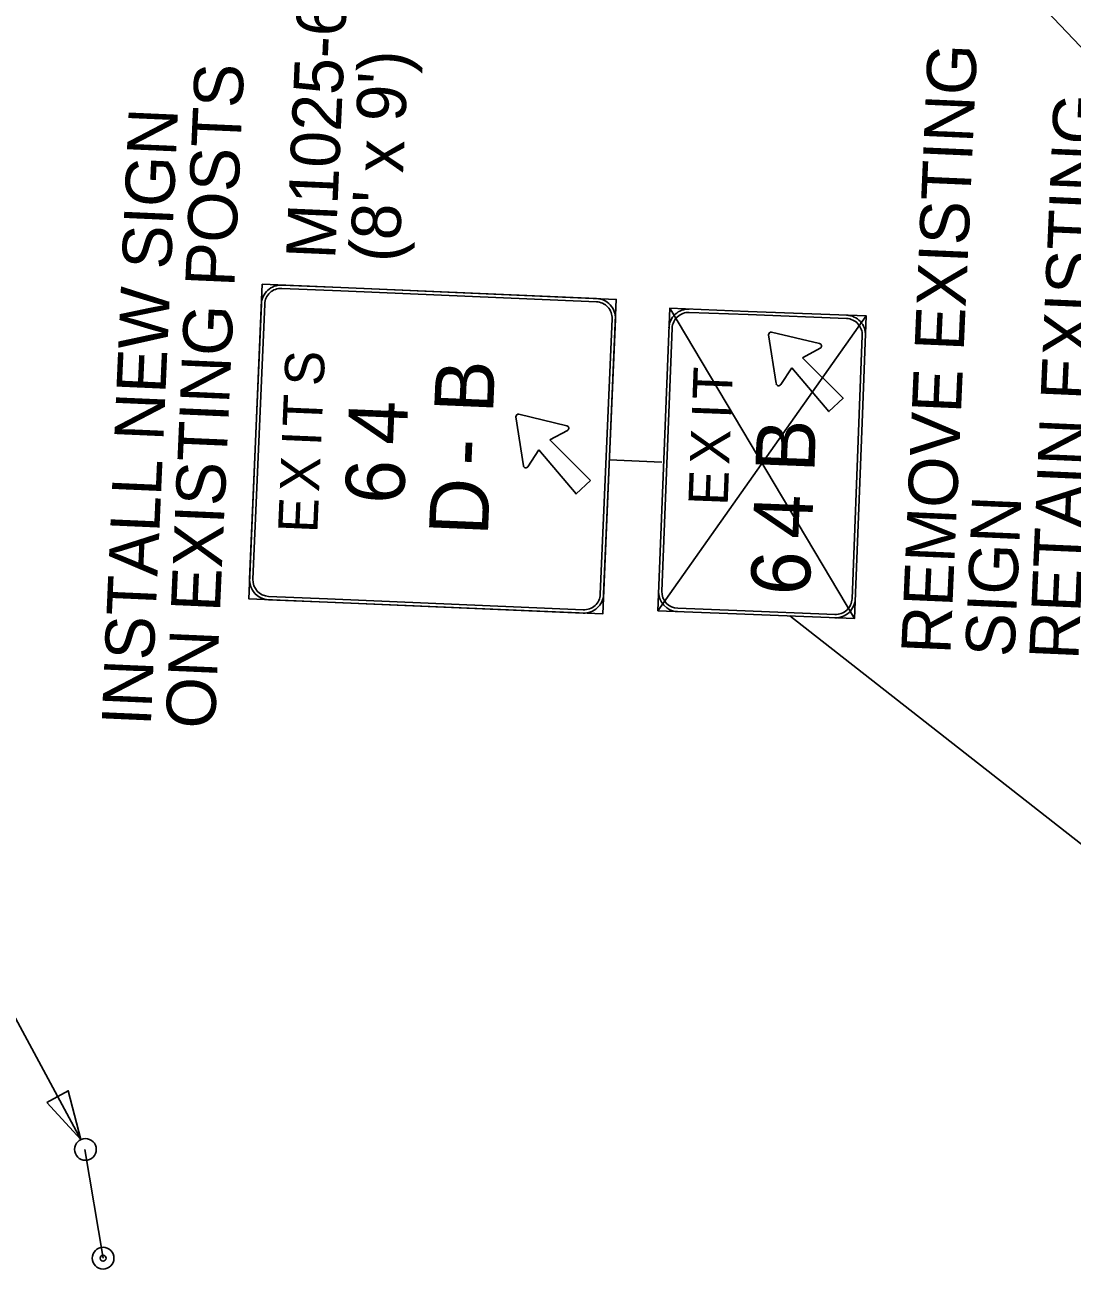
# Model space of a CAD drawing. Extents: x -5665 to 1997148, y 4 to 812485.
# Drawn here: x 1970479 to 1971011, y 802415 to 803047 of the extents above; entities that cross this region are included whole.
import ezdxf

# ---------------------------------------------------------------- set-up
doc = ezdxf.new("R2010")
doc.units = 0
for name, color, linetype in [('RD_EX_Misc', 7, 'Continuous'), ('RD_PD_Final_TX', 7, 'Continuous'), ('RD_SHT_TX', 7, 'Continuous'), ('RD_Sketch10', 7, 'Continuous')]:
    doc.layers.add(name, color=color, linetype=linetype)

msp = doc.modelspace()

# ---------------------------------------------------------------- linework, layer by layer
at = {"layer": 'RD_EX_Misc'}
for p, q in [((1970865.79, 803193.85), (1971154.39, 802889.22)), ((1970867.18, 802747.15), (1971101.66, 802563.6))]:
    msp.add_line(p, q, dxfattribs=at)
at = {"layer": 'RD_PD_Final_TX'}
msp.add_lwpolyline([(1970489.71, 802499.96), (1970500.58, 802505.87), (1970507, 802481.11)], close=True, dxfattribs=at)
at = {"layer": 'RD_SHT_TX'}
for p, q in [((1970900.11, 802745.86), (1970806.17, 802903.46)), ((1970800.18, 802749.76), (1970906.09, 802899.57)), ((1970728.06, 802848.26), (1970731.87, 802823.48)), ((1970753.96, 802843.76), (1970729.59, 802849.67)), ((1970745.3, 802836.57), (1970754.26, 802841.45)), ((1970765.92, 802815.9), (1970745.3, 802836.57)), ((1970507, 802481.11), (1970320.4, 802827.19)), ((1970734.14, 802822.98), (1970739.77, 802831.49)), ((1970802.21, 802825.32), (1970775.51, 802826.46)), ((1970508.94, 802476.01), (1970518.27, 802420.8))]:
    msp.add_line(p, q, dxfattribs=at)
for points in [[(1970639.12, 802913.99), (1970599.16, 802915.69), (1970592.34, 802755.84), (1970632.3, 802754.14), (1970632.3, 802754.14)], [(1970609.15, 802915.27), (1970639.12, 802913.99)], [(1970639.05, 802912.32), (1970609.08, 802913.6)], [(1970768.93, 802906.78), (1970639.05, 802912.32)], [(1970772.17, 802748.17), (1970778.99, 802908.02), (1970639.12, 802913.99)], [(1970639.12, 802913.99), (1970769, 802908.45)], [(1970592.76, 802765.83), (1970598.73, 802905.7)], [(1970600.4, 802905.63), (1970594.43, 802765.76)], [(1970846.14, 802901.9), (1970806.17, 802903.46), (1970800.18, 802749.76), (1970840.15, 802748.2), (1970840.15, 802748.2), (1970840.15, 802748.2)], [(1970770.93, 802758.23), (1970776.9, 802898.1)], [(1970778.57, 802898.03), (1970772.6, 802758.16)], [(1970846.07, 802900.24), (1970816.1, 802901.41)], [(1970896.04, 802898.29), (1970846.07, 802900.24)], [(1970846.07, 802900.24), (1970846.07, 802900.24), (1970846.07, 802900.24)], [(1970904.15, 802849.61), (1970906.09, 802899.57), (1970846.14, 802901.9)], [(1970896.04, 802898.29), (1970896.04, 802898.29), (1970896.04, 802898.29)], [(1970807.44, 802893.4), (1970802.24, 802759.68)], [(1970807.44, 802893.4), (1970807.44, 802893.4), (1970807.44, 802893.4)], [(1970856.42, 802889.95), (1970860.32, 802865.18)], [(1970857.66, 802890.15), (1970857.66, 802890.15), (1970857.66, 802890.15)], [(1970882.34, 802885.55), (1970857.95, 802891.36)], [(1970902.48, 802849.67), (1970904.04, 802889.64)], [(1970873.71, 802878.32), (1970882.65, 802883.24)], [(1970873.71, 802878.32), (1970894.41, 802857.73), (1970894.41, 802857.73), (1970894.41, 802857.73)], [(1970862.6, 802864.69), (1970868.2, 802873.22)], [(1970894.41, 802857.73), (1970887.11, 802850.99), (1970868.2, 802873.22)], [(1970728.06, 802848.26), (1970731.87, 802823.48)], [(1970753.96, 802843.76), (1970729.59, 802849.67)], [(1970898.83, 802755.92), (1970902.48, 802849.67)], [(1970900.11, 802745.86), (1970904.15, 802849.61)], [(1970902.48, 802849.67), (1970902.48, 802849.67), (1970902.48, 802849.67)], [(1970904.15, 802849.61), (1970904.15, 802849.61), (1970904.15, 802849.61)], [(1970745.3, 802836.57), (1970754.26, 802841.45)], [(1970745.3, 802836.57), (1970765.92, 802815.9), (1970765.92, 802815.9)], [(1970734.14, 802822.98), (1970739.77, 802831.49)], [(1970765.92, 802815.9), (1970758.6, 802809.18), (1970739.77, 802831.49)], [(1970739.77, 802831.49), (1970758.6, 802809.18), (1970765.92, 802815.9)], [(1970602.4, 802757.08), (1970632.37, 802755.8)], [(1970632.3, 802754.14), (1970602.33, 802755.41)], [(1970632.3, 802754.14), (1970772.17, 802748.17), (1970772.17, 802748.17)], [(1970762.18, 802748.59), (1970632.3, 802754.14)], [(1970632.37, 802755.8), (1970762.25, 802750.26)], [(1970810.24, 802751.03), (1970840.22, 802749.86)], [(1970810.24, 802751.03), (1970810.24, 802751.03), (1970810.24, 802751.03)], [(1970898.83, 802755.92), (1970898.83, 802755.92), (1970898.83, 802755.92)], [(1970840.15, 802748.2), (1970900.11, 802745.86), (1970900.11, 802745.86), (1970900.11, 802745.86)], [(1970840.22, 802749.86), (1970890.18, 802747.92)], [(1970840.22, 802749.86), (1970840.22, 802749.86), (1970840.22, 802749.86)]]:
    msp.add_lwpolyline(points, dxfattribs=at)
for centre in [(1970509.3, 802476.08), (1970518.27, 802420.8)]:
    msp.add_circle(centre, 5.54, dxfattribs=at)
for centre, radius, start, end in [((1970608.72, 802905.28), 10, 87.55709, 177.5573), ((1970608.72, 802905.28), 8.33, 87.55709, 177.5573), ((1970768.58, 802898.46), 8.33, 357.55715, 87.55736), ((1970768.58, 802898.46), 10, 357.55715, 87.55736), ((1970815.77, 802893.08), 10, 87.76926, 177.76947), ((1970815.77, 802893.08), 8.33, 87.76926, 177.76947), ((1970895.71, 802889.96), 8.33, 357.76932, 87.76953), ((1970895.71, 802889.96), 10, 357.76932, 87.76953), ((1970857.66, 802890.15), 1.25, 76.5917, 188.947), ((1970882.05, 802884.33), 1.25, 298.80738, 76.5917), ((1970861.56, 802865.37), 1.25, 188.9473, 326.73162), ((1970729.29, 802848.45), 1.25, 76.37895, 188.73483), ((1970729.29, 802848.45), 1.25, 76.37895, 188.73483), ((1970753.66, 802842.55), 1.25, 298.59521, 76.37895), ((1970753.66, 802842.55), 1.25, 298.59521, 76.37895), ((1970733.1, 802823.67), 1.25, 188.73513, 326.51945), ((1970733.1, 802823.67), 1.25, 188.73513, 326.51945), ((1970602.75, 802765.4), 10, 177.5573, 267.55694), ((1970602.75, 802765.4), 8.33, 177.5573, 267.55694), ((1970762.61, 802758.58), 10, 267.55694, 357.55715), ((1970762.61, 802758.58), 8.33, 267.55694, 357.55715), ((1970810.56, 802759.36), 10, 177.76947, 267.76911), ((1970810.56, 802759.36), 8.33, 177.76947, 267.76911), ((1970890.5, 802756.24), 10, 267.76911, 357.76932), ((1970890.5, 802756.24), 8.33, 267.76911, 357.76932)]:
    msp.add_arc(centre, radius, start, end, dxfattribs=at)
at = {"layer": 'RD_Sketch10'}
msp.add_circle((1970518.27, 802420.8), 1.5, dxfattribs=at)

# ---------------------------------------------------------------- texts
at = {"layer": 'RD_SHT_TX'}
for s, height, rotation, p in [('M1025-64D-B', 25, 87.4728, (1970636.19, 802928.04)), ('REMOVE EXISTING', 25, 87.4728, (1970948.75, 802727.4)), ("(8' x 9')", 25, 87.4728, (1970668.7, 802926.6)), ('ON EXISTING POSTS', 25, 87.4728, (1970575.03, 802689.51)), ('RETAIN EXISTING', 25, 87.4728, (1971013.78, 802724.53)), ('INSTALL NEW SIGN', 25, 87.4728, (1970542.51, 802690.95)), ('S', 20, 87.55709, (1970630.3, 802863.72)), ('B', 30, 87.55709, (1970716.42, 802849.8)), ('T', 20, 87.76926, (1970837.71, 802856.79)), ('T', 20, 87.55709, (1970629.41, 802842.87)), ('4', 30, 87.55709, (1970672.36, 802833.72)), ('I', 20, 87.76926, (1970837.33, 802847.17)), ('X', 20, 87.76926, (1970836.42, 802823.82)), ('B', 30, 87.76926, (1970879.63, 802819.77)), ('I', 20, 87.55709, (1970629, 802833.25)), ('-', 30, 87.55709, (1970715.28, 802823.16)), ('X', 20, 87.55709, (1970628.01, 802809.9)), ('6', 30, 87.55709, (1970671.08, 802803.65)), ('D', 30, 87.55709, (1970713.77, 802787.62)), ('E', 20, 87.76926, (1970835.61, 802802.96)), ('4', 30, 87.76926, (1970878.32, 802786.04)), ('E', 20, 87.55709, (1970627.12, 802789.05)), ('SIGN', 25, 87.4728, (1970981.27, 802725.96)), ('6', 30, 87.76926, (1970877.2, 802757.23))]:
    msp.add_text(s, height=height, rotation=rotation, dxfattribs=at).set_placement(p)

doc.saveas('drawing.dxf')
